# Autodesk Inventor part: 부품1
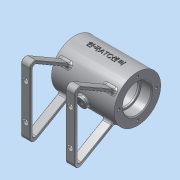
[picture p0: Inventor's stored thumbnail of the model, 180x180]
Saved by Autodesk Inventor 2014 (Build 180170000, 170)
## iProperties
Created: 2016-03
Part Number: 부품1
Material: 알루미늄 6061
Document SubType Name: Modeling
Designer: 406-9
Density: 2.71 g/cm^3
Appearance: 알루미늄 - 평지
Mass: 213.519 g
Surface Area: 333.701 cm^2
Volume: 78.7893 cm^3
Author: 406-9
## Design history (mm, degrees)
sketch "스케치1"
  geometry: L1 (-35, 0)-(35, 0); L2 (-35, 0)-(-35, 26); L3 (-35, 26)-(35, 26); L4 (35, 26)-(35, 0); 1 further point
  constraints: 8 end point, 2 perpendicular, 1 horizontal, 1 midpoint, 1 parallel
  dimensions: "d0" = 70 distance of L1.start L1.end; "d1" = 35 distance of point (0, 0) L1.end; "d2" = 26 distance of L1.start L2.end
revolve "회전1" sketch "스케치1" stored, may be unused: angle "d3" = 90 deg
sketch "스케치2"
  geometry: L1 (-35, -26)-(-35, 26) reference; L2 (35, -26)-(35, 26) reference; L3 (-35, 0)-(35, 0); L4 (-35, 16)-(-23.3, 16); L5 (-23, 15.7)-(-23, 14); L6 (-23, 14)-(-21, 14); L7 (-21, 14)-(-21, 18); L8 (-18, 21)-(18, 21); L9 (21, 18)-(21, 14); L10 (21, 14)-(23, 14); L11 (23, 14)-(23, 15.7); L12 (23.3, 16)-(35, 16); L13 (-35, 16)-(-35, 0); L14 (-35, 0)-(35, 0); L15 (35, 0)-(35, 16); A1 r 0.3 centre (-23.3, 15.7) between (-23, 15.7) and (-23.3, 16); A2 r 0.3 centre (23.3, 15.7) between (23.3, 16) and (23, 15.7); A3 r 3 centre (-18, 18) between (-18, 21) and (-21, 18); A4 r 3 centre (18, 18) between (21, 18) and (18, 21); 1 further point
  constraints: 26 end point, 8 point on circle, 8 tangent, 7 parallel, 4 centre point, 3 perpendicular, 2 collinear, 2 equal radius, 2 midpoint, 2 point on line
  dimensions: "d4" = 28 diameter of L6 L3; "d5" = 32 diameter of L4 L3; "d6" = 42 diameter of L8 L3; "d7" = 28 diameter of L10 L3; "d8" = 32 diameter of L12 L3; "d9" = 12 distance between parallel lines of L1 L5; "d10" = 2 distance between parallel lines of L5 L7; "d11" = 2 distance between parallel lines of L11 L9; "d12" = 42 distance between parallel lines of L7 L9; "d13" = 0.3 radius of A1; "d14" = 3 radius of A3
revolve "회전2" sketch "스케치2" stored, may be unused: angle "d15" = 90 deg
node "작업 평면1"
sketch "스케치3"
  geometry: C1 r 5 at (0, 0); 1 further point
  constraints: 1 centre point, 1 coincident
  dimensions: "d17" = 10 diameter of C1
extrude "돌출1" join sketch "스케치3" stored distance "d18" = 10; taper "d19" = 0 deg
hole "구멍1" diameter "d22" = 5.188; stored, may be unused: countersink angle "d26" = 90 deg, drill point angle "d28" = 118 deg; dims "d20" = 10, "d21" = 10, "d23" = 20, "d24" = 4, "d25" = 2, "d27" = 20
fillet "모깎기1" dims "d29" = 2
sketch "스케치5"
  geometry: L1 (0, 0)-(0, 26); C1 r 16 at (0, 0) reference; 1 further point
  constraints: 2 end point, 1 point on line, 1 vertical, 1 vertical alignment, 1 other
  dimensions: "d30" = 21 distance of C1.centre point (0, 21)
hole "구멍2" sketch "스케치5" at (0, 21) diameter "d31" = 3.242; stored, may be unused: countersink angle "d35" = 90 deg, drill point angle "d37" = 118 deg; dims "d32" = 8, "d33" = 4, "d34" = 2, "d36" = 10
node "작업 평면2"
sketch "스케치6"
  geometry: L1 (-20, 16.613)-(-57.5, 38.264); L2 (-65, 33.934)-(-65, -33.934); L3 (-57.5, -38.264)-(-20, -16.613); L4 (0, 0)-(-65, 0); L5 (-21.791, 14.183)-(-57.5, 34.8); L6 (-62, 32.202)-(-62, -32.202); L7 (-57.5, -34.8)-(-21.791, -14.183); A1 r 26 centre (0, 0) between (-20, 16.613) and (-20, -16.613) reference; A2 r 5 centre (-60, 33.934) between (-57.5, 38.264) and (-65, 33.934); A3 r 5 centre (-60, -33.934) between (-65, -33.934) and (-57.5, -38.264); A4 r 3 centre (-59, 32.202) between (-57.5, 34.8) and (-62, 32.202); A5 r 3 centre (-59, -32.202) between (-62, -32.202) and (-57.5, -34.8); A6 r 26 centre (0, 0) between (-20, 16.613) and (-21.791, 14.183); A7 r 26 centre (0, 0) between (-21.791, -14.183) and (-20, -16.613); 1 further point
  constraints: 16 point on circle, 14 end point, 8 tangent, 6 centre point, 2 coincident, 2 equal radius, 1 midpoint, 1 perpendicular, 1 vertical, 1 other
  dimensions: "d43" = 30 deg angle of L4 L1; "d45" = 65 distance from line of L2 point (0, 0); "d46" = 45 distance from line of L2 L1.start; "d47" = 3 distance between parallel lines of L2 L6; "d48" = 5 radius of A2; "d49" = 3 radius of A4; "d52" = 3 distance between parallel lines of L1 L5; "d53" = 3 distance between parallel lines of L7 L3
extrude "돌출2" join sketch "스케치6" distance "d54" = 10; taper "d55" = 0 deg
sketch "스케치7"
  geometry: L1 (0, 64.403)-(0, 0) reference; L2 (-40, -1.732)-(-40, 66.135) reference; L3 (-40, -1.732)-(-50, -1.732) reference; L4 (-50, -1.732)-(-50, 66.135) reference; L5 (-40, 66.135)-(-50, 66.135) reference; C1 r 3 at (5, 52.202); C2 r 3 at (5, 12.202); C3 r 3 at (-45, 12.202); C4 r 3 at (-45, 52.202); 1 further point
  constraints: 4 centre point
  dimensions: "d56" = 6 diameter of C1; "d57" = 20 vertical distance of point (-20, 32.202) C1.centre; "d58" = 5 distance from line of L1 C1.centre; "d59" = 6 diameter of C2; "d60" = 20 vertical distance of C2.centre point (-20, 32.202); "d61" = 5 distance from line of C2.centre L1; "d62" = 6 diameter of C3; "d63" = 20 vertical distance of C3.centre point (-20, 32.202); "d64" = 5 distance from line of L4 C3.centre; "d65" = 6 diameter of C4; "d66" = 5 distance from line of C4.centre L4; "d67" = 20 vertical distance of point (-20, 32.202) C4.centre
extrude "돌출3" cut sketch "스케치7" distance "d68" = 10; taper "d69" = 0 deg
sketch "스케치8"
  geometry: L1 (0, 0)-(-26, 0); L2 (0, 0)-(-28.012, -7.506); 1 further point
  constraints: 4 end point, 1 horizontal, 1 horizontal alignment, 1 other
  dimensions: "d70" = 29 distance of L1.start L2.end; "d89" = 15 deg angle of L1 L2
node "작업 평면6"
sketch "스케치13"
  geometry: L1 (-35, 26)-(35, 26) reference; L2 (-35, -26)-(-35, 26) reference; 2 further points
  constraints: 1 other
  dimensions: "d85" = 26 distance from line of L1 point (0, 0); "d86" = 35 distance from line of point (0, 0) L2
feature "엠보싱1" sketch "스케치13" dims "d4" = 28, "d5" = 32, "d6" = 42, "d7" = 28, "d8" = 32, "d9" = 12, "d10" = 2, "d11" = 2, "d12" = 42, "d13" = 0.3, "d14" = 3, "d87" = 0.5, "d88" = 0
node "작업 평면8"
sketch "스케치15"
  geometry: C1 r 6 at (0, 0); 1 further point
  constraints: 1 centre point, 1 coincident
  dimensions: "d90" = 12 diameter of C1
extrude "돌출5" join sketch "스케치15" stored distance "d91" = 10; taper "d92" = 0 deg
hole "구멍4" diameter "d95" = 5.188; stored, may be unused: countersink angle "d99" = 90 deg, drill point angle "d101" = 118 deg; dims "d93" = 10, "d94" = 10, "d96" = 29, "d97" = 4, "d98" = 2, "d100" = 29
fillet "모깎기3" dims "d102" = 2
sketch "스케치16"
  geometry: 1 further point
fillet "모깎기4" dims "d103" = 0.5
fillet "모깎기5" dims "d104" = 3
chamfer "모따기1" distance "d105" = 1; stored, may be unused: second distance "d106" = 2, angle "d107" = 45 deg
node "솔리드1"
pattern_circular "원형 패턴1" dims angle "d39" = 360 deg
mirror "대칭1"
mirror "대칭2"
node "투영된 루프1"
node "투영된 루프2"
other parameters: "d16" = 29
